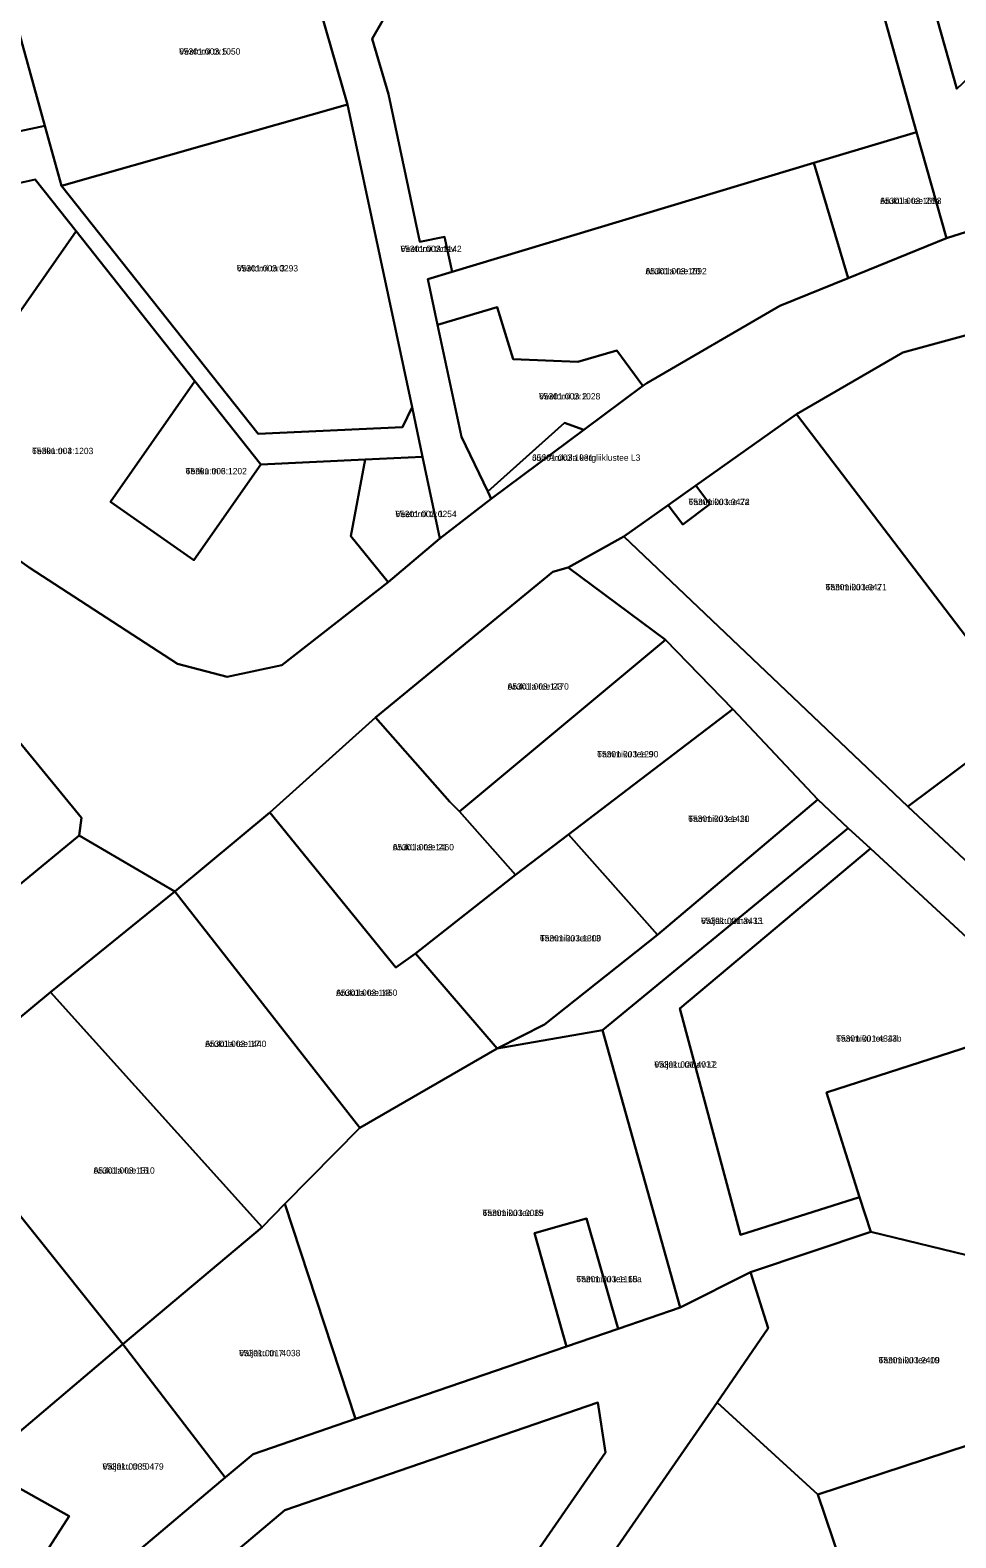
# Model space of a CAD drawing. Extents: x 543236 to 563717, y 6566033 to 6588992.
# Drawn here: x 550962.8 to 551182, y 6579920 to 6580276.9 of the extents above; entities that cross this region are included whole.
import ezdxf

# ---------------------------------------------------------------- set-up
doc = ezdxf.new("R2010")
doc.units = 0
for name, color, linetype in [('L_AADRESS', 7, 'Continuous'), ('PIIR', 7, 'Continuous'), ('TUNNUS', 7, 'Continuous')]:
    doc.layers.add(name, color=color, linetype=linetype)

msp = doc.modelspace()

# ---------------------------------------------------------------- linework, layer by layer
at = {"layer": 'PIIR'}
for points in [[(551095.74, 6580511.04), (551108.64, 6580519.51), (551124.62, 6580464.86), (551142.47, 6580403.99), (551182.24, 6580262.99), (551295.09, 6580369.3), (551353.48, 6580369.68), (551355.03, 6580364.33), (551297.07, 6580364.3), (551186.35, 6580260), (551194.02, 6580232.16), (551179.83, 6580227.7), (551172.67, 6580252.8), (551170.71, 6580259.79), (551150.49, 6580332.06), (551142.76, 6580359.55), (551114.9, 6580456.31), (551109.31, 6580472.28)], [(551142.47, 6580403.99), (551230.67, 6580429.36), (551264.83, 6580426.74), (551284.76, 6580425.21), (551295.09, 6580369.3), (551182.24, 6580262.99)], [(550943.99, 6580249.52), (550950.53, 6580264.18), (550943.16, 6580292.29), (550912.15, 6580392.53), (550921.84, 6580397.2), (550923.15, 6580397.8), (550955.58, 6580292.71), (550966.27, 6580254.24)], [(551150.49, 6580332.06), (551170.71, 6580259.79), (551172.67, 6580252.8), (551148.35, 6580245.49), (551062.73, 6580219.72), (551060.92, 6580228.02), (551055.05, 6580226.8), (551047.61, 6580261.76), (551043.8, 6580274.89), (551048.66, 6580283.36), (551045.33, 6580295.03), (551051.07, 6580296.86), (551102.72, 6580317.9), (551094.58, 6580345.22), (551140.81, 6580359.01), (551142.76, 6580359.55)], [(550988.47, 6580302.22), (550994.85, 6580280.53), (551028.98, 6580290.31), (551037.91, 6580259.34), (550970.22, 6580240.05), (550966.27, 6580254.24), (550955.58, 6580292.71)], [(551059.82, 6580156.6), (551055.71, 6580175.88), (551053.2, 6580187.63), (551037.91, 6580259.34), (551028.98, 6580290.31), (551037.17, 6580292.66), (551045.33, 6580295.03), (551048.66, 6580283.36), (551043.8, 6580274.89), (551047.61, 6580261.76), (551055.05, 6580226.8), (551060.92, 6580228.02), (551062.73, 6580219.72), (551056.95, 6580217.98), (551059.26, 6580207.12), (551064.91, 6580180.68), (551071.13, 6580167.66), (551071.95, 6580165.96)], [(550826.03, 6580245.87), (550833.66, 6580258), (550845.94, 6580257.95), (550863.3, 6580254.93), (550912.87, 6580242.52), (550943.99, 6580249.52), (550966.27, 6580254.24), (550970.22, 6580240.05), (551016.76, 6580181.34), (551050.92, 6580182.92), (551053.2, 6580187.63), (551055.71, 6580175.88), (551042.12, 6580175.25), (551017.38, 6580174.1), (551001.75, 6580193.85), (550973.67, 6580229.32), (550963.98, 6580241.56), (550912.7, 6580230.19), (550897.52, 6580234), (550839.87, 6580251.89), (550831.84, 6580241.83)], [(550970.22, 6580240.05), (551037.91, 6580259.34), (551053.2, 6580187.63), (551050.92, 6580182.92), (551016.76, 6580181.34)], [(551148.35, 6580245.49), (551172.67, 6580252.8), (551179.83, 6580227.7), (551156.54, 6580218.23)], [(551056.95, 6580217.98), (551062.73, 6580219.72), (551148.35, 6580245.49), (551156.54, 6580218.23), (551140.35, 6580211.64), (551108.85, 6580193.36), (551107.91, 6580192.74), (551101.69, 6580201.11), (551092.5, 6580198.36), (551077.19, 6580199.04), (551073.4, 6580211.33), (551059.26, 6580207.12)], [(550897.52, 6580234), (550912.7, 6580230.19), (550963.98, 6580241.56), (550973.67, 6580229.32), (550932.76, 6580170.82), (550889.8, 6580201.63)], [(550973.67, 6580229.32), (551001.75, 6580193.85), (550981.77, 6580165.28), (551001.54, 6580151.45), (551017.38, 6580174.1), (551042.12, 6580175.25), (551038.7, 6580157.14), (551047.58, 6580146.25), (551022.35, 6580126.59), (551009.41, 6580123.79), (550997.63, 6580126.9), (550962.51, 6580149.69), (550932.76, 6580170.82)], [(551059.26, 6580207.12), (551073.4, 6580211.33), (551077.19, 6580199.04), (551092.5, 6580198.36), (551101.69, 6580201.11), (551107.91, 6580192.74), (551093.88, 6580182.3), (551089.28, 6580183.95), (551071.13, 6580167.66), (551064.91, 6580180.68)], [(551001.75, 6580193.85), (551017.38, 6580174.1), (551001.54, 6580151.45), (550981.77, 6580165.28)], [(551103.37, 6580157.06), (551113.87, 6580164.49), (551117.37, 6580159.86), (551123.74, 6580164.67), (551120.4, 6580169.1), (551144.3, 6580186.03), (551198.94, 6580114.26), (551170.63, 6580093.09)], [(551071.13, 6580167.66), (551089.28, 6580183.95), (551093.88, 6580182.3), (551071.95, 6580165.96)], [(551042.12, 6580175.25), (551055.71, 6580175.88), (551059.82, 6580156.6), (551047.58, 6580146.25), (551038.7, 6580157.14)], [(551113.87, 6580164.49), (551120.4, 6580169.1), (551123.74, 6580164.67), (551117.37, 6580159.86)], [(551086.53, 6580148.68), (551090.17, 6580149.68), (551113.27, 6580132.6), (551064.48, 6580091.91), (551062.18, 6580094.23), (551044.52, 6580114.2)], [(550921.01, 6580142.97), (550946.21, 6580125.37), (550974.9, 6580090.47), (550974.4, 6580086.27), (550959.52, 6580074.03), (550943.75, 6580093.23), (550937.18, 6580087.81), (550902.82, 6580129.58)], [(551113.27, 6580132.6), (551129.21, 6580116.19), (551090.3, 6580086.5), (551077.74, 6580076.92), (551064.48, 6580091.91)], [(551044.52, 6580114.2), (551062.18, 6580094.23), (551064.48, 6580091.91), (551077.74, 6580076.92), (551054.01, 6580058.35), (551049.38, 6580055), (551019.52, 6580091.69)], [(551129.21, 6580116.19), (551149.3, 6580094.77), (551111.37, 6580062.77), (551090.3, 6580086.5)], [(551073.39, 6580035.86), (551084.62, 6580041.5), (551111.37, 6580062.77), (551149.3, 6580094.77), (551156.53, 6580088.03), (551098.32, 6580040.16)], [(551019.52, 6580091.69), (551049.38, 6580055), (551054.01, 6580058.35), (551073.39, 6580035.86), (551040.81, 6580017.05), (550997.06, 6580072.97)], [(551054.01, 6580058.35), (551077.74, 6580076.92), (551090.3, 6580086.5), (551111.37, 6580062.77), (551084.62, 6580041.5), (551073.39, 6580035.86)], [(551098.32, 6580040.16), (551156.53, 6580088.03), (551161.8, 6580083.2), (551116.6, 6580045.3), (551131, 6579991.7), (551159.2, 6580000.6), (551161.85, 6579992.4), (551133.4, 6579982.91), (551116.72, 6579974.55)], [(551116.6, 6580045.3), (551161.8, 6580083.2), (551205.42, 6580042.89), (551151.36, 6580025.41), (551159.2, 6580000.6), (551131, 6579991.7)], [(550997.06, 6580072.97), (551040.81, 6580017.05), (551023.11, 6579999.08), (551017.74, 6579993.54), (550967.61, 6580049.2)], [(550967.61, 6580049.2), (551017.74, 6579993.54), (550984.71, 6579965.8), (550937.77, 6580024.46)], [(551161.85, 6579992.4), (551159.2, 6580000.6), (551151.36, 6580025.41), (551205.42, 6580042.89), (551246.4, 6580004.97), (551187.22, 6579986.3)], [(551023.11, 6579999.08), (551040.81, 6580017.05), (551073.39, 6580035.86), (551098.32, 6580040.16), (551116.72, 6579974.55), (551102, 6579969.49), (551094.56, 6579995.57), (551089.19, 6579994.08), (551082.25, 6579992.11), (551088.82, 6579968.6), (551089.8, 6579965.3), (551039.8, 6579948.12)], [(550937.77, 6580024.46), (550984.71, 6579965.8), (550957.62, 6579942.87), (550910.96, 6580002.29)], [(551187.22, 6579986.3), (551246.4, 6580004.97), (551267.49, 6579983.82), (551251.5, 6579964.99), (551251.37, 6579944.96), (551199.86, 6579927.81), (551196.3, 6579904.7), (551161.9, 6579893.15), (551149.33, 6579930.21), (551200.34, 6579947.01)], [(551017.74, 6579993.54), (551023.11, 6579999.08), (551039.8, 6579948.12), (551015.6, 6579939.82), (551008.95, 6579934.25), (550984.71, 6579965.8)], [(551082.25, 6579992.11), (551089.19, 6579994.08), (551094.56, 6579995.57), (551102, 6579969.49), (551089.8, 6579965.3), (551088.82, 6579968.6)], [(551125.44, 6579951.99), (551137.56, 6579969.64), (551133.4, 6579982.91), (551161.85, 6579992.4), (551187.22, 6579986.3), (551200.34, 6579947.01), (551149.33, 6579930.21)], [(550826.55, 6579936), (550857.34, 6579960.82), (550891, 6579986.48), (550890.99, 6579977.58), (550895.48, 6579972.74), (550915.23, 6579958.93), (550924.72, 6579966.72), (550950.65, 6579937), (550971.99, 6579925.08), (550964.69, 6579913.68), (550944.69, 6579926.58), (550933.69, 6579916.4), (550951.68, 6579890.26), (550927.75, 6579910.64), (550906.83, 6579888.46), (550903.2, 6579892.67), (550877.66, 6579874.62), (550862.38, 6579885.09)], [(550950.65, 6579937), (550957.62, 6579942.87), (550984.71, 6579965.8), (551008.95, 6579934.25), (550975.94, 6579906.43), (550964.69, 6579913.68), (550971.99, 6579925.08)], [(550968.23, 6579880.32), (550991.32, 6579845.76), (551087.84, 6579865.86), (551074.62, 6579904.89), (551099.05, 6579940.2), (551097.21, 6579951.99), (551023.06, 6579926.52)], [(550968.23, 6579880.32), (551023.06, 6579926.52), (551097.21, 6579951.99), (551099.05, 6579940.2), (551074.62, 6579904.89), (551087.84, 6579865.86), (550991.32, 6579845.76)], [(551149.33, 6579930.21), (551161.9, 6579893.15), (551101.37, 6579872.66), (551091.25, 6579902.56), (551125.44, 6579951.99)]]:
    msp.add_lwpolyline(points, close=True, dxfattribs=at)
for points in [[(550711.19, 6580273.31), (550745.96, 6580322.05), (550752.52, 6580316.45), (550764.37, 6580302.62), (550790.58, 6580271.87), (550826.03, 6580245.87), (550831.84, 6580241.83), (550889.8, 6580201.63), (550932.76, 6580170.82), (550962.51, 6580149.69), (550997.63, 6580126.9), (551009.41, 6580123.79), (551022.35, 6580126.59), (551047.58, 6580146.25), (551059.82, 6580156.6), (551071.95, 6580165.96), (551093.88, 6580182.3), (551107.91, 6580192.74), (551108.85, 6580193.36), (551140.35, 6580211.64), (551156.54, 6580218.23), (551179.83, 6580227.7), (551194.02, 6580232.16)], [(551220.66, 6580214.61), (551169.46, 6580200.63), (551144.3, 6580186.03), (551120.4, 6580169.1), (551113.87, 6580164.49), (551103.37, 6580157.06), (551090.17, 6580149.68), (551086.53, 6580148.68), (551044.52, 6580114.2), (551019.52, 6580091.69), (550997.06, 6580072.97), (550974.4, 6580086.27), (550974.9, 6580090.47), (550946.21, 6580125.37), (550921.01, 6580142.97), (550868.04, 6580179.87), (550859.83, 6580185.66), (550831.9, 6580205.09), (550819.17, 6580214.65), (550793.89, 6580233.64), (550770.89, 6580250.91), (550746.93, 6580262.58), (550732.02, 6580271.89)], [(551247.33, 6580021.45), (551170.63, 6580093.09), (551198.94, 6580114.26), (551144.3, 6580186.03), (551169.46, 6580200.63), (551220.66, 6580214.61)], [(551205.42, 6580042.89), (551161.8, 6580083.2), (551156.53, 6580088.03), (551149.3, 6580094.77), (551129.21, 6580116.19), (551113.27, 6580132.6), (551090.17, 6580149.68), (551103.37, 6580157.06), (551170.63, 6580093.09), (551247.33, 6580021.45)], [(550809.1, 6579914.26), (550793.9, 6579942.99), (550832.2, 6579965.58), (550833.2, 6579967.28), (550831.1, 6579970.29), (550838.27, 6579977.17), (550881.8, 6580010.78), (550931.8, 6580051.27), (550939.03, 6580057.18), (550959.52, 6580074.03), (550974.4, 6580086.27), (550997.06, 6580072.97), (550967.61, 6580049.2), (550937.77, 6580024.46), (550910.96, 6580002.29), (550891, 6579986.48), (550857.34, 6579960.82), (550826.55, 6579936), (550862.38, 6579885.09)], [(550975.94, 6579906.43), (551008.95, 6579934.25), (551015.6, 6579939.82), (551039.8, 6579948.12), (551089.8, 6579965.3), (551102, 6579969.49), (551116.72, 6579974.55), (551133.4, 6579982.91), (551137.56, 6579969.64), (551125.44, 6579951.99), (551091.25, 6579902.56)]]:
    msp.add_lwpolyline(points, dxfattribs=at)

# ---------------------------------------------------------------- texts
at = {"layer": 'L_AADRESS'}
for s, p in [('Veetorni tn 5', (550998.04, 6580271.13)), ('Aruküla tee 20a', (551164.09, 6580235.76)), ('Veetorni tänav', (551050.46, 6580224.4)), ('Veetorni tn 3', (551011.71, 6580219.79)), ('Aruküla tee 20', (551108.5, 6580219.11)), ('Veetorni tn 2', (551083.29, 6580189.49)), ('Teriku tn 4', (550963.21, 6580176.55)), ('Jüri-Aruküla kergliiklustee L3', (551081.64, 6580174.96)), ('Teriku tn 6', (550999.58, 6580171.78)), ('Tammiku tee 2a', (551118.68, 6580164.48)), ('Veetorni tn 1', (551049.26, 6580161.63)), ('Tammiku tee 2', (551151.15, 6580144.32)), ('Aruküla tee 23', (551075.84, 6580120.79)), ('Tammiku tee 9', (551097.06, 6580104.76)), ('Tammiku tee 11', (551118.62, 6580089.48)), ('Aruküla tee 21', (551048.63, 6580082.74)), ('Väljaku tänav L1', (551121.65, 6580065.32)), ('Tammiku tee 13', (551083.5, 6580061.18)), ('Aruküla tee 19', (551035.23, 6580048.29)), ('Tammiku tee 13b', (551153.65, 6580037.45)), ('Aruküla tee 17', (551004.21, 6580036.2)), ('Väljaku tänav L2', (551110.59, 6580031.29)), ('Aruküla tee 15', (550977.76, 6580006.21)), ('Tammiku tee 15', (551069.91, 6579996.16)), ('Tammiku tee 15a', (551092.12, 6579980.5)), ('Väljaku tn 7', (551012.25, 6579962.98)), ('Tammiku tee 19', (551163.7, 6579961.3)), ('Väljaku tn 5', (550979.88, 6579936.12))]:
    msp.add_text(s, height=1.5, dxfattribs=at).set_placement(p)
at = {"layer": 'TUNNUS'}
for s, p in [('65301:003:1050', (550998.04, 6580271.13)), ('65301:003:1093', (551164.09, 6580235.76)), ('65301:003:1142', (551050.46, 6580224.4)), ('65301:003:0293', (551011.71, 6580219.79)), ('65301:003:1092', (551108.5, 6580219.11)), ('65301:003:1028', (551083.29, 6580189.49)), ('65301:003:1203', (550963.21, 6580176.55)), ('65301:003:1031', (551081.64, 6580174.96)), ('65301:003:1202', (550999.58, 6580171.78)), ('65301:003:0472', (551118.68, 6580164.48)), ('65301:003:0254', (551049.26, 6580161.63)), ('65301:003:0471', (551151.15, 6580144.32)), ('65301:003:1470', (551075.84, 6580120.79)), ('65301:003:1290', (551097.06, 6580104.76)), ('65301:003:1430', (551118.62, 6580089.48)), ('65301:003:1460', (551048.63, 6580082.74)), ('65301:001:3433', (551121.65, 6580065.32)), ('65301:003:1300', (551083.5, 6580061.18)), ('65301:003:1450', (551035.23, 6580048.29)), ('65301:001:4344', (551153.65, 6580037.45)), ('65301:003:1440', (551004.21, 6580036.2)), ('65301:001:4037', (551110.59, 6580031.29)), ('65301:003:1310', (550977.76, 6580006.21)), ('65301:003:0089', (551069.91, 6579996.16)), ('65301:003:1168', (551092.12, 6579980.5)), ('65301:001:4038', (551012.25, 6579962.98)), ('65301:003:2400', (551163.7, 6579961.3)), ('65301:003:0479', (550979.88, 6579936.12))]:
    msp.add_text(s, height=1.5, dxfattribs=at).set_placement(p)

doc.saveas('drawing.dxf')
